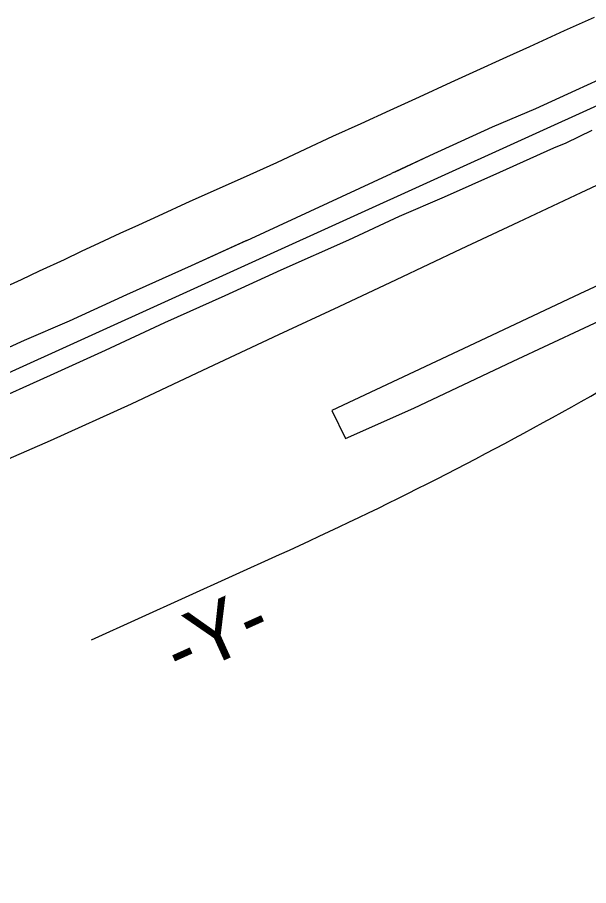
# Model space of a CAD drawing. Extents: x 2243531 to 2252747, y 658714 to 667210.
# Drawn here: x 2249406 to 2249747, y 663262 to 663780 of the extents above; entities that cross this region are included whole.
import ezdxf

# ---------------------------------------------------------------- set-up
doc = ezdxf.new("R2010")
doc.units = 0
for name, color, linetype in [('Exist Roads EOP', 7, 'Continuous'), ('Prop Horizontal Alignment', 7, 'Continuous'), ('Prop Horizontal Alignment Direction Label', 7, 'Continuous')]:
    doc.layers.add(name, color=color, linetype=linetype)

msp = doc.modelspace()

# ---------------------------------------------------------------- linework, layer by layer
at = {"layer": 'Exist Roads EOP'}
msp.add_line((2249542.9, 663647.1), (2249629.32, 663687.08), dxfattribs=at)
for points in [[(2249750.29, 663780.29), (2249732.43, 663772.23), (2249711.61, 663762.73), (2249697.93, 663756.48), (2249677.79, 663747.34), (2249664.81, 663741.42), (2249645.78, 663732.66), (2249628.27, 663724.73), (2249610.93, 663716.72), (2249594.12, 663709.11), (2249578.08, 663701.61), (2249560.66, 663693.52), (2249544.69, 663686.38), (2249522.95, 663676.61), (2249508.94, 663670.28), (2249490, 663661.61), (2249478.41, 663656.28), (2249467.2, 663651.22), (2249454.82, 663645.46), (2249444.08, 663640.44), (2249433.9, 663635.61), (2249419.1, 663628.75), (2249408.32, 663623.66), (2249397.37, 663618.54)], [(2249750.29, 663780.29), (2249732.43, 663772.23), (2249711.61, 663762.73), (2249697.93, 663756.48), (2249677.79, 663747.34), (2249664.81, 663741.42), (2249645.78, 663732.66), (2249628.27, 663724.73), (2249610.93, 663716.72), (2249594.12, 663709.11), (2249578.08, 663701.61), (2249560.66, 663693.52), (2249544.69, 663686.38), (2249522.95, 663676.61), (2249508.94, 663670.28), (2249490, 663661.61), (2249478.41, 663656.28), (2249467.2, 663651.22), (2249454.82, 663645.46), (2249444.08, 663640.44), (2249433.9, 663635.61), (2249419.1, 663628.75), (2249408.32, 663623.66), (2249397.37, 663618.54)], [(2250076.16, 663777.96), (2250011.04, 663745.73), (2249959.41, 663720.2), (2249871.12, 663677.1), (2249809.32, 663646.75), (2249741.67, 663615.28), (2249682.29, 663587.16), (2249593.6, 663545.55), (2249601.8, 663528.84), (2249642.54, 663547.1), (2249701.92, 663575.09), (2249765.85, 663604.94)], [(2250076.16, 663777.96), (2250011.04, 663745.73), (2249959.41, 663720.2), (2249871.12, 663677.1), (2249809.32, 663646.75), (2249741.67, 663615.28), (2249682.29, 663587.16), (2249593.6, 663545.55), (2249601.8, 663528.84), (2249642.54, 663547.1), (2249701.92, 663575.09), (2249765.85, 663604.94)], [(2249759.98, 663746.21), (2249739.06, 663736.71), (2249715.24, 663725.78), (2249689.32, 663714.81), (2249652.07, 663697.64), (2249629.32, 663687.08)], [(2249759.98, 663746.21), (2249739.06, 663736.71), (2249715.24, 663725.78), (2249689.32, 663714.81), (2249652.07, 663697.64), (2249630.81, 663687.77)], [(2249748.92, 663712.77), (2249733.4, 663705.13), (2249725.89, 663702.15), (2249693.85, 663687.77), (2249660.73, 663672.87), (2249633.88, 663661.38), (2249603.61, 663647.21), (2249563.33, 663629.32), (2249529.77, 663614.02), (2249493.93, 663597.97), (2249458.47, 663581.35), (2249425.6, 663566.47), (2249386.57, 663548.98), (2249351.1, 663533.06), (2249316.09, 663516.96), (2249277.98, 663499.39), (2249240.81, 663482.13), (2249208.98, 663467.59), (2249166.03, 663447.67), (2249125.56, 663429.26)], [(2249748.92, 663712.77), (2249733.4, 663705.13), (2249725.89, 663702.15), (2249693.85, 663687.77), (2249660.73, 663672.87), (2249633.88, 663661.38), (2249603.61, 663647.21), (2249563.33, 663629.32), (2249529.77, 663614.02), (2249493.93, 663597.97), (2249458.47, 663581.35), (2249425.6, 663566.47), (2249386.57, 663548.98), (2249351.1, 663533.06), (2249316.09, 663516.96), (2249277.98, 663499.39), (2249240.81, 663482.13), (2249208.98, 663467.59), (2249166.03, 663447.67), (2249125.89, 663429.41)], [(2249128.12, 663399.86), (2249149.1, 663408.54), (2249173.29, 663418.91), (2249195.22, 663428.26), (2249222.36, 663439.97), (2249251, 663452.41), (2249280.38, 663464.92), (2249306.39, 663476.13), (2249330.07, 663486.34), (2249354.62, 663496.92), (2249378.7, 663507.27), (2249425.8, 663527.78), (2249474.22, 663549.62), (2249516.79, 663569.63), (2249561.98, 663591), (2249598.11, 663607.75), (2249632.26, 663623.87), (2249670.79, 663642.03), (2249705.32, 663658.14), (2249742.5, 663675.66), (2249776.59, 663691.66)], [(2249128.35, 663399.96), (2249149.1, 663408.54), (2249173.29, 663418.91), (2249195.22, 663428.26), (2249222.36, 663439.97), (2249251, 663452.41), (2249280.38, 663464.92), (2249306.39, 663476.13), (2249330.07, 663486.34), (2249354.62, 663496.92), (2249378.7, 663507.27), (2249425.8, 663527.78), (2249474.22, 663549.62), (2249516.79, 663569.63), (2249561.98, 663591), (2249598.11, 663607.75), (2249632.26, 663623.87), (2249670.79, 663642.03), (2249705.32, 663658.14), (2249742.5, 663675.66), (2249776.59, 663691.66)], [(2249542.9, 663647.1), (2249509.73, 663631.88), (2249471.24, 663614.74), (2249436.95, 663599.03), (2249410.14, 663587.36), (2249375.48, 663571.69), (2249346.95, 663558.33), (2249298.73, 663535.83), (2249272.97, 663524.36), (2249255.33, 663516.02), (2249215.08, 663497.83), (2249189.93, 663486.88), (2249155.17, 663472.43), (2249148.14, 663469.51), (2249123.21, 663458.27)], [(2249542.41, 663646.88), (2249509.73, 663631.88), (2249471.24, 663614.74), (2249436.95, 663599.03), (2249410.14, 663587.36), (2249375.48, 663571.69), (2249346.95, 663558.33), (2249298.73, 663535.83), (2249272.97, 663524.36), (2249255.33, 663516.02), (2249215.08, 663497.83), (2249189.93, 663486.88), (2249155.17, 663472.43), (2249148.14, 663469.51), (2249123.21, 663458.27)]]:
    msp.add_lwpolyline(points, dxfattribs=at)
at = {"layer": 'Prop Horizontal Alignment'}
for p, q in [((2247500.8, 662705.02), (2249793.08, 663746.29)), ((2249450.36, 663408.68), (2249562.54, 663459.61))]:
    msp.add_line(p, q, dxfattribs=at)
msp.add_arc((2248611.75, 665553.89), 2300, 294.41783, 304.80379, dxfattribs=at)

# ---------------------------------------------------------------- texts
at = {"layer": 'Prop Horizontal Alignment Direction Label'}
msp.add_text('-Y-', height=35, rotation=24.2751, dxfattribs=at).set_placement((2249502.94, 663384.49))

doc.saveas('drawing.dxf')
